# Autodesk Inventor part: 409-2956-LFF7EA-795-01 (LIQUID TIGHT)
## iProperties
Created: 2010-09
Part Number: 409-2956-LFF7EA-795-01 (LIQUID TIGHT)
Material: 3/4" LIQUID TIGHT
Document SubType Name: Modeling
Designer: S. Boerckel
Engineer: Steve Boerckel
Mass: 232.246 g
Surface Area: 912.875 cm^2
Volume: 165.89 cm^3
Density: 1.4 g/cm^3
Description: LIQUID TIGHT
Length: 22.603 in
Author: S. Boerckel
Revision Number: 0
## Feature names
1. Sweep1
